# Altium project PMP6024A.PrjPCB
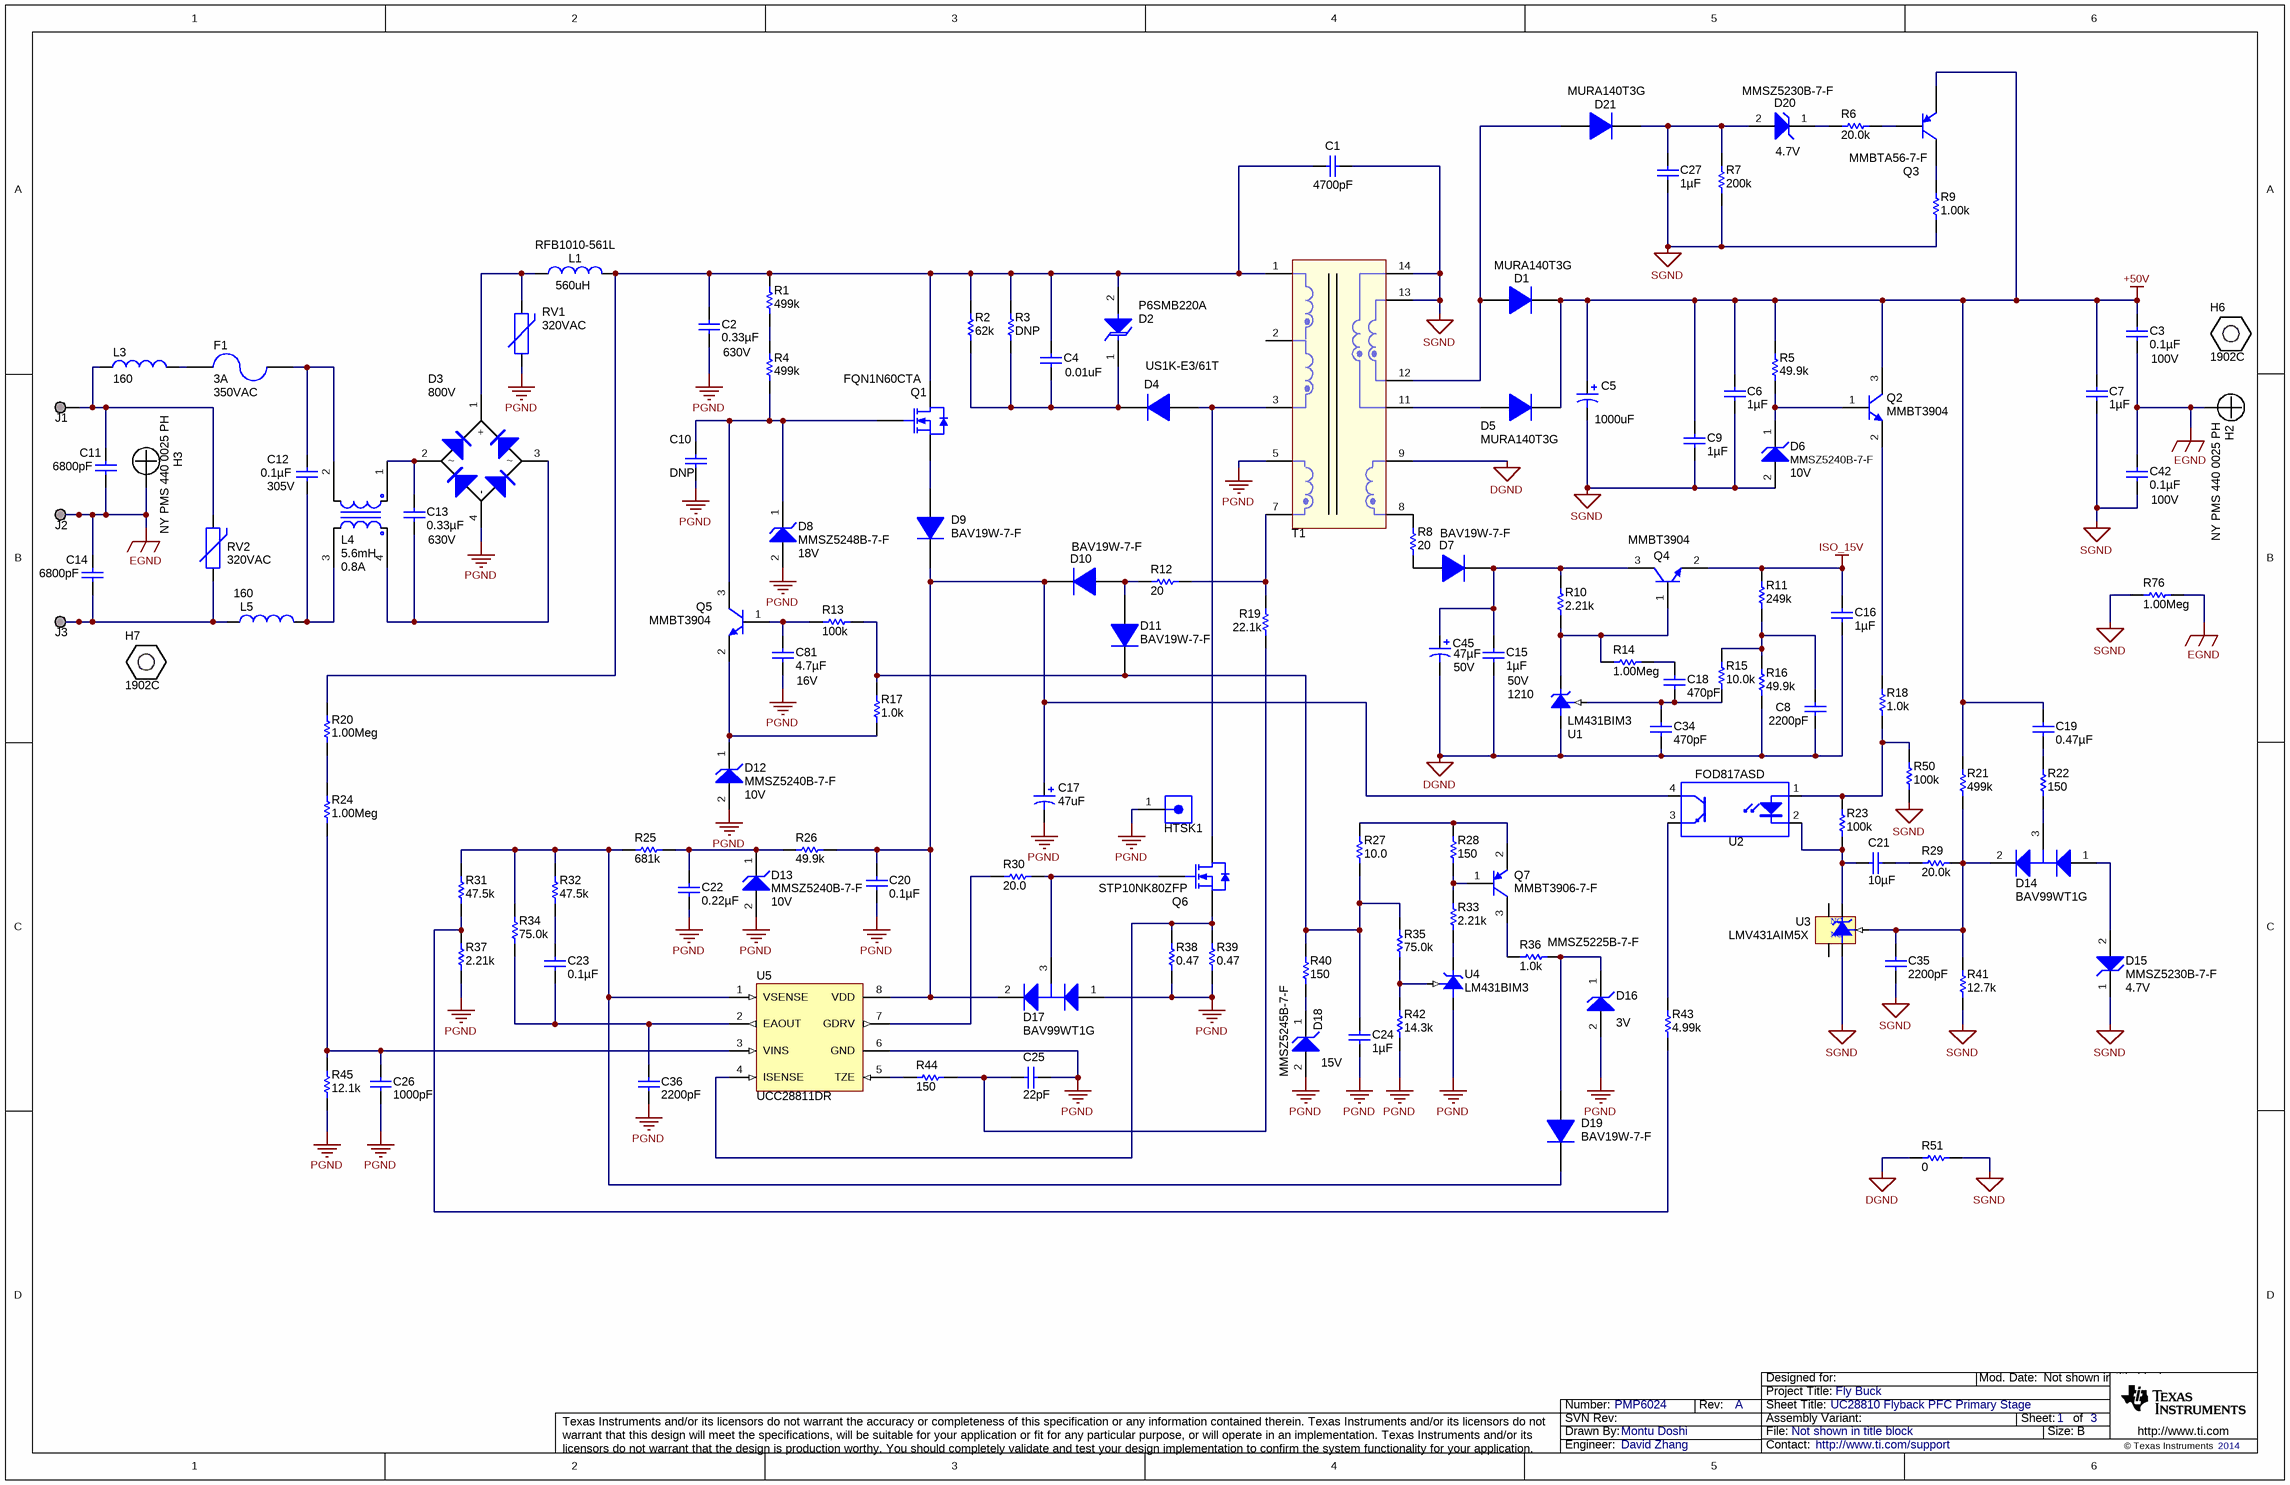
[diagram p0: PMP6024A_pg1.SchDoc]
TechSupport: http://www.ti.com/support; SCH_Rev: A; PRJ_Title: Fly Buck; PRJ_Number: PMP6024; PRJ_Engineer: David Zhang; PCB_Rev: A; PCB_Layout: Kerry Murphy; CopyrightYear: 2014
3 sheets, 186 parts. Net scope: global (net labels, ports and power ports of the same name join across sheets).
Board file: PMP6024A.PcbDoc
Sheets:
  PMP6024A_pg1.SchDoc
  PMP6024A_pg2.SchDoc
  PMP6024A_Hardware.SchDoc

## Sheet PMP6024A_pg1.SchDoc: UC28810 Flyback PFC Primary Stage
size 431 x 279 mm; Date: Not shown in title block; ApprovedBy: Not shown in title block; CheckedBy: Not shown in title block; Author: Not shown in title block; CompanyName: Not shown in title block; DrawnBy: Montu Doshi; Engineer: Not shown in title block; Organization: Not shown in title block; Address1: Not shown in title block; Address2: Not shown in title block; Address3: Not shown in title block; Address4: Not shown in title block; DocumentNumber: 1; Revision: Use project parameter SCH_Rev; SheetNumber: 1; SheetTotal: 3; PageSetup: Record=PageOptions|CenterHorizontal=True|CenterVertical=True|PrintScale=1.00|XCorrection=1.00|YCorrection=1.00|PrintKind=0|BorderSize=5000000|LeftOffset=0|BottomOffset=0|Orientation=2|PaperLength=1000|PaperWidth=1000|Scale=100|PaperSource=15|PrintQuality=600|MediaType=1|DitherType=10|PaperKind=Letter|PrintScaleMode=1

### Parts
C1  value 4700pF  [Cap_NP_16Dx5W-10LS]  (hidden comment: VY1472M63Y5UQ63V0)
C2  ValueDisplayed: 0.33µF  Value2: 630V  [B32922_14.5mm]  (hidden comment: B32922C3334M)
C3  ValueDisplayed: 0.1µF  Value2: 100V  [1206]  (hidden comment: GRM319R72A104KA01D)
C4  value 0.01uF  [1808]  (hidden comment: VJ1808Y103KXGAT)
C5  value 1000uF  [CAP_POL-16.5Dx37.5T-7.5LS_Horz]  (hidden comment: UPW1J102MHD6)
C6  ValueDisplayed: 1µF  [1206]  (hidden comment: GRM31CR72A105KA01L)
C7  ValueDisplayed: 1µF  [1206]  (hidden comment: GRM31CR72A105KA01L)
C8  ValueDisplayed: 2200pF  [0603_HV]  (hidden comment: C0603C222K5RACTU)
C9  ValueDisplayed: 1µF  [1206]  (hidden comment: GRM31CR72A105KA01L)
C10  DNP  [0603_HV]
C11  value 6800pF  [Cap_NP_14.5Lx5W-10LS]  (hidden comment: VY2682M59Y5US63V0)
C12  value 0.1µF  Voltage Rating - AC: 305V  [Cap_NP_13Lx6W-10LS]  (hidden comment: B32921C3104M)
C13  ValueDisplayed: 0.33µF  Value2: 630V  [B32922_14.5mm]  (hidden comment: B32922C3334M)
C14  value 6800pF  [Cap_NP_14.5Lx5W-10LS]  (hidden comment: VY2682M59Y5US63V0)
C15  ValueDisplayed: 1µF  Value2: 50V  [1210]  (hidden comment: GRM32RR71H105KA01L)
C16  ValueDisplayed: 1µF  [1206]  (hidden comment: GRM31CR72A105KA01L)
C17  value 47uF  [Cap_Pol_5Dx11T-2LS]  (hidden comment: EEU-EB1E470S)
C18  ValueDisplayed: 470pF  [0603_HV]  (hidden comment: GRM1885C2A471JA01D)
C19  ValueDisplayed: 0.47µF  [1206]  (hidden comment: GRM31MR72A474KA35L)
C20  ValueDisplayed: 0.1µF  [0603_HV]  (hidden comment: GRM188R71H104KA93D)
C21  ValueDisplayed: 10µF  [1206]  (hidden comment: GRM31CR71A106KA01L)
C22  ValueDisplayed: 0.22µF  [0603_HV]  (hidden comment: GRM188R71E224KA88D)
C23  ValueDisplayed: 0.1µF  [0603_HV]  (hidden comment: GRM188R71H104KA93D)
C24  ValueDisplayed: 1µF  [1206]  (hidden comment: GRM31CR72A105KA01L)
C25  ValueDisplayed: 22pF  [0603_HV]  (hidden comment: GRM1885C2A220JA01D)
C26  ValueDisplayed: 1000pF  [0603_HV]  (hidden comment: GRM188R72A102KA01D)
C27  ValueDisplayed: 1µF  [1206]  (hidden comment: GRM31CR72A105KA01L)
C34  ValueDisplayed: 470pF  [0603_HV]  (hidden comment: GRM1885C2A471JA01D)
C35  ValueDisplayed: 2200pF  [0603_HV]  (hidden comment: C0603C222K5RACTU)
C36  ValueDisplayed: 2200pF  [0603_HV]  (hidden comment: C0603C222K5RACTU)
C42  ValueDisplayed: 0.1µF  Value2: 100V  [1206]  (hidden comment: GRM319R72A104KA01D)
C45  value 47µF  VDC_V: 50V  [Cap_Pol_6.3Dx11T-2.5LS_horz]  (hidden comment: UPW1H470MED)
C81  ValueDisplayed: 4.7µF  VDC_V: 16V  [0805_HV]  (hidden comment: C2012X5R1C475K125AC)
D1  MURA140T3G  [SMA]
D2  P6SMB220A  [SMB]
D3  value 800V  [KBPM]  (hidden comment: 2KBP08M-E4/51)
D4  US1K-E3/61T  [SMA]
D5  MURA140T3G  [SMA]
D6  MMSZ5240B-7-F  value 10V  [SOD-123]
D7  BAV19W-7-F  [SOD-123]
D8  MMSZ5248B-7-F  value 18V  [SOD-123]
D9  BAV19W-7-F  [SOD-123]
D10  BAV19W-7-F  [SOD-123]
D11  BAV19W-7-F  [SOD-123]
D12  MMSZ5240B-7-F  value 10V  [SOD-123]
D13  MMSZ5240B-7-F  value 10V  [SOD-123]
D14  BAV99WT1G  [SOT-323]
D15  MMSZ5230B-7-F  value 4.7V  [SOD-123]
D16  MMSZ5225B-7-F  value 3V  [SOD-123]
D17  BAV99WT1G  [SOT-323]
D18  MMSZ5245B-7-F  value 15V  [SOD-123]
D19  BAV19W-7-F  [SOD-123]
D20  MMSZ5230B-7-F  value 4.7V  [SOD-123]
D21  MURA140T3G  [SMA]
F1  value 3A  Value1: 350VAC  [Fuse_447series]  (hidden comment: 0447003.YXP)
H2  NY PMS 440 0025 PH  [NY PMS 440 0025 PH]
H3  NY PMS 440 0025 PH  [NY PMS 440 0025 PH]
H6  1902C  [Keystone_1902C]
H7  1902C  [Keystone_1902C]
HTSK1  7141DG  [Htsk_7147DG]  (value not drawn)
J1  TESTPOINT  [Hole_R110D70]  (value not drawn)  (no BOM)
J2  TESTPOINT  [Hole_R110D70]  (value not drawn)  (no BOM)
J3  TESTPOINT  [Hole_R110D70]  (value not drawn)  (no BOM)
L1  value 560uH  [Indt_RL5480-4]  (hidden comment: RFB1010-561L)
L3  value 160  [1206]  (hidden comment: HI1206T161R-10)
L4  value 5.6mH  Value1: 0.8A  [Schaffner_EH20-0.8-02-5M6]  (hidden comment: EH20-0.8-02-5M6)
L5  value 160  [1206]  (hidden comment: HI1206T161R-10)
Q1  FQN1N60CTA  [TO92_modified]
Q2  MMBT3904  [MF03A_N]
Q3  MMBTA56-7-F  [MF03A_N]
Q4  MMBT3904  [MF03A_N]
Q5  MMBT3904  [MF03A_N]
Q6  STP10NK80ZFP  [TO-220AB-wide]
Q7  MMBT3906-7-F  [MF03A_N]
R1  value 499k  [1206]  (hidden comment: CRCW1206499KFKEA)
R2  value 62k  [2512]  (hidden comment: CRCW251262K0JNEG)
R3  DNP  [2512]
R4  value 499k  [1206]  (hidden comment: CRCW1206499KFKEA)
R5  value 49.9k  [0603_HV]  (hidden comment: CRCW060349K9FKEA)
R6  value 20.0k  [0603]  (hidden comment: CRCW060320K0FKEA)
R7  value 200k  [1206]  (hidden comment: CRCW1206200KFKEA)
R8  value 20  [1206]  (hidden comment: CRCW120620R0JNEA)
R9  value 1.00k  [0603]  (hidden comment: CRCW06031K00FKEA)
R10  value 2.21k  [0603_HV]  (hidden comment: CRCW06032K21FKEA)
R11  value 249k  [0603_HV]  (hidden comment: CRCW0603249KFKEA)
R12  value 20  [1206]  (hidden comment: CRCW120620R0JNEA)
R13  value 100k  [0603_HV]  (hidden comment: CRCW0603100KFKEA)
R14  value 1.00Meg  [0603_HV]  (hidden comment: CRCW06031M00FKEA)
R15  value 10.0k  [0603_HV]  (hidden comment: CRCW060310K0FKEA)
R16  value 49.9k  [0603_HV]  (hidden comment: CRCW060349K9FKEA)
R17  value 1.0k  [0603_HV]  (hidden comment: CRCW06031K00JNEA)
R18  value 1.0k  [0603_HV]  (hidden comment: CRCW06031K00JNEA)
R19  value 22.1k  [1206]  (hidden comment: CRCW120622K1FKEA)
R20  value 1.00Meg  [1206]  (hidden comment: CRCW12061M00FKEA)
R21  value 499k  [1206]  (hidden comment: CRCW1206499KFKEA)
R22  value 150  [0805_HV]  (hidden comment: CRCW0805150RFKEA)
R23  value 100k  [0603_HV]  (hidden comment: CRCW0603100KFKEA)
R24  value 1.00Meg  [1206]  (hidden comment: CRCW12061M00FKEA)
R25  value 681k  [0603_HV]  (hidden comment: CRCW0603681KFKEA)
R26  value 49.9k  [0603_HV]  (hidden comment: CRCW060349K9FKEA)
R27  value 10.0  [0603_HV]  (hidden comment: CRCW060310R0FKEA)
R28  value 150  [0805_HV]  (hidden comment: CRCW0805150RFKEA)
R29  value 20.0k  [0603_HV]  (hidden comment: CRCW060320K0FKEA)
R30  value 20.0  [0603_HV]  (hidden comment: CRCW060320R0FKEA)
R31  value 47.5k  [0603_HV]  (hidden comment: CRCW060347K5FKEA)
R32  value 47.5k  [0603_HV]  (hidden comment: CRCW060347K5FKEA)
R33  value 2.21k  [0603_HV]  (hidden comment: CRCW06032K21FKEA)
R34  value 75.0k  [0603_HV]  (hidden comment: CRCW060375K0FKEA)
R35  value 75.0k  [0603_HV]  (hidden comment: CRCW060375K0FKEA)
R36  value 1.0k  [0603_HV]  (hidden comment: CRCW06031K00JNEA)
R37  value 2.21k  [0603_HV]  (hidden comment: CRCW06032K21FKEA)
R38  value 0.47  [1210]  (hidden comment: MCR25JZHFLR470)
R39  value 0.47  [1210]  (hidden comment: MCR25JZHFLR470)
R40  value 150  [0805_HV]  (hidden comment: CRCW0805150RFKEA)
R41  value 12.7k  [0603_HV]  (hidden comment: CRCW060312K7FKEA)
R42  ValueDisplayed: 14.3k  [0603_HV]  (hidden comment: CRCW060314K3FKEA)
R43  value 4.99k  [0603_HV]  (hidden comment: CRCW06034K99FKEA)
R44  value 150  [0805_HV]  (hidden comment: CRCW0805150RFKEA)
R45  value 12.1k  [0603_HV]  (hidden comment: CRCW060312K1FKEA)
R50  value 100k  [0603]  (hidden comment: CRCW0603100KFKEA)
R51  value 0  [1206]  (hidden comment: CRCW12060000Z0EA)
R76  value 1.00Meg  [1206]  (hidden comment: CRCW12061M00FKEA)
RV1  value 320VAC  [MOV_S14K320E2K1]  (hidden comment: S14K320E2K1)
RV2  value 320VAC  [MOV_S14K320E2K1]  (hidden comment: S14K320E2K1)
T1  (no value)  [Xfmr_ETD29H_Wurth]
U1  LM431BIM3  [MF03A_N]
U2  FOD817ASD  [FOD81XASD]
U3  LMV431AIM5X  [MF05A_N]
U4  LM431BIM3  [MF03A_N]
U5  UCC28811DR  [D0008A_N]

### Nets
+50V: C3.1 C5.1(+) C6.1 C7.1 C9.1 C19.1 D1.1(K) D5.1(K) Q2.3(C) Q3.2(E) R5.2 R21.1
DGND: C8.2 C15.2 C16.2 C34.2 C45.2(-) R16.1 R51.1 T1.9 U1.3(A)
EGND: C3.2 C11.2 C14.1 C42.1 H2.1(P1) H3.1(P1) J2.1 R76.1
ISO_15V: C16.1 Q4.2(E) R11.2
PGND: C2.2 C10.2 C17.2(-) C20.2 C22.2 C24.2 C25.1 C26.2 C36.2 C81.2 D3.4(-) D8.2(A) D12.2(A) D13.2(A) D16.2(A) D17.1(A) D18.2(A) HTSK1.1 R37.1 R38.1 R39.1 R42.1 R45.1 RV1.1 T1.5 U4.3(A) U5.6(GND)
SGND: C1.1 C5.2(-) C6.2 C7.2 C9.2 C27.2 C35.2 C42.2 D6.2(A) D15.1(K) R7.1 R9.1 R41.1 R50.1 R51.2 R76.2 T1.13 T1.14 U3.5(A)
NetC1_2: C1.2 C2.1 C4.1 D2.2(A) L1.2 Q1.2(D) R1.1 R2.2 R3.2 R20.2 T1.1
NetC4_2: C4.2 D2.1(K) D4.1(K) R2.1 R3.1
NetC8_1: C8.1 R11.1 R15.2 R16.2
NetC10_1: C10.1 D8.1(K) Q1.1(G) Q5.3(C) R4.2
NetC11_1: C11.1 J1.1 L3.1 RV2.2
NetC12_1: C12.1 F1.1 L4.2
NetC12_2: C12.2 L4.3 L5.2
NetC13_1: C13.1 D3.2 L4.1
NetC13_2: C13.2 D3.3 L4.4
NetC14_2: C14.2 J3.1 L5.1 RV2.1
NetC15_1: C15.1 C45.1(+) D7.1(K) Q4.3(C) R10.2
NetC17_1: C17.1(+) C20.1 D9.1(K) D10.1(K) D17.2(K) R26.2 U2.4(C) U5.8(VDD)
NetC18_1: C18.1 R14.1
NetC18_2: C18.2 C34.1 R15.1 U1.2(REF)
NetC19_2: C19.2 R22.2
NetC21_1: C21.1 R23.1 U2.2(K) U3.3(K)
NetC21_2: C21.2 R29.2
NetC22_1: C22.1 D13.1(K) R25.1 R26.1
NetC23_1: C23.1 R32.1
NetC23_2: C23.2 C36.1 R34.1 U5.2(EAOUT)
NetC24_1: C24.1 D11.1(K) R13.2 R17.2 R27.1 R35.2 R40.2
NetC25_2: C25.2 R19.1 R44.1
NetC26_1: C26.1 R24.1 R45.2 U5.3(VINS)
NetC27_1: C27.1 D20.2(A) D21.1(K) R7.2
NetC35_1: C35.1 D14.2(K) R21.2 R29.1 R41.2 U3.4(REF)
NetC81_1: C81.1 Q5.1(B) R13.1
NetD1_2: D1.2(A) D21.2(A) T1.12
NetD3_1: D3.1(+) L1.1 RV1.2
NetD4_2: D4.2(A) Q6.2(D) T1.3
NetD5_2: D5.2(A) T1.11
NetD6_1: D6.1(K) Q2.1(B) R5.1
NetD7_2: D7.2(A) R8.2
NetD9_2: D9.2(A) Q1.3(S)
NetD10_2: D10.2(A) D11.2(A) R12.2
NetD12_1: D12.1(K) Q5.2(E) R17.1
NetD14_1: D14.1(A) D15.2(A)
NetD14_3: D14.3(C) R22.1
NetD16_1: D16.1(K) D19.2(A) R36.2
NetD17_3: D17.3(C) Q6.1(G) R30.2
NetD18_1: D18.1(K) R40.1
NetD19_1: D19.1(K) R25.2 R31.2 R32.2 R34.2 U5.1(VSENSE)
NetD20_1: D20.1(K) R6.1
NetF1_2: F1.2 L3.2
NetQ2_2: Q2.2(E) R18.2
NetQ3_1: Q3.1(B) R6.2
NetQ3_3: Q3.3(C) R9.2
NetQ4_1: Q4.1(B) R10.1 R14.2 U1.1(K)
NetQ6_3: Q6.3(S) R38.2 R39.2 U5.4(ISENSE)
NetQ7_1: Q7.1(B) R28.1 R33.2
NetQ7_2: Q7.2(E) R27.2 R28.2
NetQ7_3: Q7.3(C) R36.1
NetR1_2: R1.2 R4.1
NetR8_1: R8.1 T1.8
NetR12_1: R12.1 R19.2 T1.7
NetR18_1: R18.1 R23.2 R50.2 U2.1(A)
NetR20_1: R20.1 R24.2
NetR30_1: R30.1 U5.7(GDRV)
NetR31_1: R31.1 R37.2 R43.1
NetR33_1: R33.1 U4.1(K)
NetR35_1: R35.1 R42.2 U4.2(REF)
NetR43_2: R43.2 U2.3(E)
NetR44_2: R44.2 U5.5(TZE)

Not connected (* = marked no-connect by the designer): T1 2 4 6 10; U3 1(NC) 2(NC)

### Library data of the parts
C1 = Capacitor: CAP, CERM, 4700pF, 500VAC, Y5U, 20%, Radial 10mm; Manufacturer: Vishay BC Components; Polarized: N; U/M: EA
C2 C13 = B32922C3334M: CAP, Film, 0.33uF, 630V, +/-20%, TH; Manufacturer: EPCOS Inc; Polarized: N; CompType: Capacitor; U/M: EA; Cap_F: 0.00000033; Tolerance_%: 20; Value1: Unknown; VDC_V: 630; TaMax_C: 110
C3 C42 = GRM319R72A104KA01D: CAP, CERM, 0.1uF, 100V, +/-10%, X7R, 1206; Manufacturer: MuRata; Polarized: N; CompType: Capacitor; U/M: EA; Cap_F: 0.0000001; Tolerance_%: 10; VDC_V: 100; TaMin_C: -55; TaMax_C: 125
C4 = Capacitor: CAP, CERM, 0.01uF, 1000V, X7R, 10%, 1808; Manufacturer: Vishay Vitramon; Alternate Manufacturer: Kemet; Alternate PartNumber: C1808C103KDRACTU; Polarized: N; U/M: EA
C5 = Capacitor_Polarized: CAP, Aluminum, 1000uF, 63V, +/-20%, Radial; Manufacturer: Panasonic Electronic Components; Polarized: Y; U/M: EA
C6 C7 C9 C16 C24 C27 = GRM31CR72A105KA01L: CAP, CERM, 1uF, 100V, +/-10%, X7R, 1206; Manufacturer: MuRata; Polarized: N; CompType: Capacitor; U/M: EA; Cap_F: 0.000001; Tolerance_%: 10; VDC_V: 100; TaMin_C: -55; TaMax_C: 125; Cap_Case: 2220
C8 C35 C36 = C0603C222K5RACTU: CAP, CERM, 2200pF, 50V, +/-10%, X7R, 0603; Manufacturer: Kemet; Polarized: N; CompType: Capacitor; U/M: EA; Cap_F: 0.0000000022; Tolerance_%: 10; Value1: Unknown; VDC_V: 50; TaMin_C: -55; TaMax_C: 125; Cap_Case: 0603
C10 = GRM188R71E473KA01D: Manufacturer: MuRata; Polarized: N; CompType: Capacitor; U/M: EA; Tolerance_%: 10; VDC_V: 25; Value2: 25V; TempCo: X7R; TaMin_C: -55; TaMax_C: 125; Cap_Case: 0603
C11 C14 = Capacitor: CAP, Safety, 6800pF, 300VAC, Y5U, 20%, Radial, Disc; Manufacturer: Vishay BC Components; Polarized: N; U/M: EA; Description: CAP CER 6800PF 300V 20% RADIAL; TempCo: Y5U (E); Ratings: X1Y2
C12 = Capacitor: CAP, FILM, 0.1uF, 305VAC, Radial; Manufacturer: EPCOS Inc; Polarized: N; U/M: EA; Voltage Rating - DC: 630V; Description: CAP FILM 0.1UF 305VAC RADIAL; Tolerance_%: ±20%; Dielectric Material: Polypropylene
C15 = GRM32RR71H105KA01L: CAP, CERM, 1uF, 50V, +/-10%, X7R, 1210; Manufacturer: MuRata; Polarized: N; CompType: Capacitor; U/M: EA; Cap_F: 0.000001; Tolerance_%: 10; ESR_Ohm: 0.003; Value1: 0.003 ohm; VDC_V: 50; TaMin_C: -30; TaMax_C: 85
C17 = Capacitor_Polarized: CAP, Aluminum, 47uF, 25V, +/-20%, Radial; Manufacturer: Panasonic Electronic Components; Polarized: Y; U/M: EA
C18 C34 = GRM1885C2A471JA01D: CAP, CERM, 470pF, 100V, +/-5%, C0G/NP0, 0603; Manufacturer: MuRata; Polarized: N; CompType: Capacitor; U/M: EA; Cap_F: 0.00000000047; Tolerance_%: 5; Value1: Unknown; VDC_V: 100; TaMin_C: -55; TaMax_C: 125; Cap_Case: 0603
C19 = GRM31MR72A474KA35L: CAP, CERM, 0.47uF, 100V, +/-10%, X7R, 1206; Manufacturer: MuRata; Polarized: N; CompType: Capacitor; U/M: EA; Cap_F: 0.00000047; Tolerance_%: 10; VDC_V: 100; TaMin_C: -55; TaMax_C: 125
C20 C23 = GRM188R71H104KA93D: CAP, CERM, 0.1uF, 50V, +/-10%, X7R, 0603; Manufacturer: MuRata; Polarized: N; CompType: Capacitor; U/M: EA; Cap_F: 0.0000001; Tolerance_%: 10; VDC_V: 50; TaMin_C: -55; TaMax_C: 125; Cap_Case: 0603
C21 = GRM31CR71A106KA01L: CAP, CERM, 10uF, 10V, +/-10%, X5R, 1206; Manufacturer: MuRata; Polarized: N; CompType: Capacitor; U/M: EA; Cap_F: 0.00001; Tolerance_%: 10; TaMin_C: -55; TaMax_C: 85
C22 = GRM188R71E224KA88D: CAP, CERM, 0.22uF, 25V, +/-10%, X7R, 0603; Manufacturer: MuRata; Polarized: N; CompType: Capacitor; U/M: EA; Cap_F: 0.00000022; Tolerance_%: 10; VDC_V: 25; TaMin_C: -55; TaMax_C: 125; Cap_Case: 0603
C25 = GRM1885C2A220JA01D: CAP, CERM, 22pF, 100V, +/-5%, C0G/NP0, 0603; Manufacturer: MuRata; Polarized: N; CompType: Capacitor; U/M: EA; Cap_F: 0.000000000022; Tolerance_%: 5; VDC_V: 100; TaMin_C: -55; TaMax_C: 125; Cap_Case: 0603
C26 = GRM188R72A102KA01D: CAP, CERM, 1000pF, 100V, +/-10%, X7R, 0603; Manufacturer: MuRata; Polarized: N; CompType: Capacitor; U/M: EA; Cap_F: 0.000000001; Tolerance_%: 10; VDC_V: 100; TaMin_C: -55; TaMax_C: 125; Cap_Case: 0603
C45 = Capacitor_Polarized: CAP, Alum, 47uF, 50V, +/-20%, Radial; Manufacturer: Nichicon; Polarized: Y; U/M: EA; Description: CAP ALUM 47UF 50V 20% RADIAL; Ripple Current: 300mA; Tolerance_%: ±20%; Impedance: 430 mOhm; Lifetime @ Temp.: 2000 Hrs @ 105°C
C81 = EMK212BJ475KG-T: CAP, CERM, 4.7uF, 16V, +/-10%, X5R, 0805; Manufacturer: TDK Corporation; Polarized: N; CompType: Capacitor; Value: 4.7µF; U/M: EA; Cap_F: 0.0000047; Tolerance_%: ±10%; Value1: Unknown; TaMin_C: -55; TaMax_C: 85; Cap_Case: 0805; Description: CAP CER 4.7UF 16V 10% X5R 0805
D1 D5 D21 = Diode: Diode, Ultrafas, 400V, 2A, SMA; Manufacturer: ON Semiconductor; U/M: EA
D2 = TVS_Diode_Uni: Diode, TVS, Uni, 600W, 220V, Unidirection, 5%, SMB; Manufacturer: Littelfuse Inc; Alternate PartNumber: SMBJ220A; U/M: EA
D3 = Diode_Bridge_Pos1_Neg4_AC23: Diode, Switching-Bridge, 800V, 2A, SIP; Manufacturer: Vishay Semiconductor Diodes Division; CompType: Diode Bridge; U/M: EA
D4 = Diode: Diode, Ultrafast, 800V, 1A, SMA; Manufacturer: Vishay Semiconductor Diodes Division; Alternate Manufacturer: Diodes Inc; Alternate PartNumber: US1K-13-F; U/M: EA
D6 D12 D13 = MMSZ5240B-7-F: Diode, Zener, 10V, 500mW, SOD-123; Manufacturer: Diodes Inc.; U/M: EA; Power_W: 0.5; Vz_V: 10; Value1: 0.5W; RJA_CperW: 350
D7 D9-D11 D19 = Diode: Diode, Fast, 100V, 200mA, SOD-123; Manufacturer: Diodes Inc; Alternate Manufacturer: ON Semiconductor; Alternate PartNumber: MMSD4148T3G; U/M: EA
D8 = MMSZ5248B-7-F: Diode, Zener, 18V, 500mW, SOD-123; Manufacturer: Diodes Inc.; U/M: EA; Power_W: 0.5; Vz_V: 18; Value1: 0.5W; RJA_CperW: 350
D14 D17 = BAV99WT1G: Diode, P-N, 70V, 0.2A, SOT-323; Manufacturer: Fairchild Semiconductor; Value: 0.63V; U/M: EA; Vf_V: 0.63; Io_A: 0.2; Vr_V: 70; TJmax_C: 150
D15 D20 = MMSZ5230B-7-F: Diode, Zener, 4.7V, 500mW, SOD-123; Manufacturer: Diodes Inc.; U/M: EA; Power_W: 0.5; Vz_V: 4.7; Value1: 0.5W; RJA_CperW: 350
D16 = MMSZ5225B-7-F: Diode, Zener, 3V, 500mW, SOD-123; Manufacturer: Diodes Inc.; U/M: EA; Power_W: 0.5; Vz_V: 3; Value1: 0.5W; RJA_CperW: 350
D18 = MMSZ5245B-7-F: Diode, Zener, 15V, 500mW, SOD-123; Manufacturer: Diodes Inc.; U/M: EA; Power_W: 0.5; Vz_V: 15; Value1: 0.5W; RJA_CperW: 350
F1 = Fuse: Fuse, 3A, 350VAC, Board Mount; Manufacturer: Littelfuse Inc; U/M: EA
H2 H3 = Chassis Screw: Machine Screw, Round, #4-40 x 1/4, Nylon, Philips panhead; Manufacturer: B&F Fastener Supply; CompType: Hardware; SymbolCreator: codlsc; U/M: EA
H6 H7 = 1902C: Standoff, Hex, 0.5"L #4-40 Nylon; Manufacturer: Keystone; CompType: Hardware
HTSK1 = Htsk_7141DG: HTSK, Aavid P/N 7141DG, TO-220 Vert, PCB mount; Manufacturer: Aavid Thermalloy; CompType: Heatsink; U/M: EA; Shape: Rectangular; Thermal Resistance @ Forced Air Flow: 10.0°C/W @ 200 LFM; Material Finish: Tin; Thermal Resistance @ Natural: 20.3°C/W; Power Dissipation @ Temperature Rise: 1W @ 30°C; Attachment Method: Clip and PC Pin
J1-J3 = TESTPOINT: TEST POINT.  No entry in BOM.
L1 = Inductor: Inductor, 560uH, 1.05A, Radial; Manufacturer: Coilcraft; U/M: EA
L3 L5 = Inductor: Inductor, Ferrite EMI Chip, 160 Ohm @ 100KHz, 6A, 18m ohm, SMT; Manufacturer: Laird-Signal Integrity Products; U/M: EA
L4 = INDUCTOR_COUPLED: Coupled Inductor, 5.6mH, 0.8A, 245m ohm, +/-15%, Through Hole; Manufacturer: Schaffner EMC Inc; U/M: EA
Q1 = MOSFET_N: MOSFET, N-CH, 600V, 300mA, TO-92; Manufacturer: Fairchild Semiconductor; U/M: EA
Q2 Q4 Q5 = MMBT3904, Fairchild Semiconductor: Transistor, NPN, 40V, 0.2A, SOT-23; Alternate Manufacturer: None; CompType: BJT; U/M: EA; PNP: 0; NPN: 1; Vceo_V: 40; Vcesat1_V: 0.2; Value: 0.2V; HfeMax: 300
Q3 = PNP: Transistor, PNP, 80V, SOT23; Manufacturer: Diodes Inc; CompType: Bipolar Transistor; U/M: EA; Vce Saturation (Max) @ Ib, Ic: 250mV @ 10mA, 100mA; Power - Max: 300mW; Current - Collector (Ic) (Max): 500mA; DC Current Gain (hFE) (Min) @ Ic, Vce: 100 @ 100mA, 1V; Frequency - Transition: 50MHz; Description: TRANSISTOR PNP 80V SOT23-3
Q6 = MOSFET_N: MOSFET, N-CH, 800V, 9A, TO-220FP; Manufacturer: STMicroelectronics; U/M: EA
Q7 = MMBT3906-7-F, Diodes Inc.: Transistor, PNP, 40V, 0.2A, SOT-23; Alternate Manufacturer: None; CompType: BJT; U/M: EA; PNP: 1; NPN: 0; Vceo_V: 40; Vcesat1_V: 0.25; Value: 0.25V; IcRated_A: 0.2; HfeMax: 400
R1 R4 R21 = CRCW1206499KFKEA: RES, 499k ohm, 1%, 0.25W, 1206; Manufacturer: Vishay-Dale; Alternate Manufacturer: Any; Alternate PartNumber: Equivalent; CompType: Resistor; Res_ohm: 499000; Tolerance_%: 1; Power_W: 0.25; VDC_V: 200; TempCo: 100 ppm/C; EIA_Code: E96; U/M: EA
R2 = Resistor: RES, 62k ohm, 5%, 1W, 2512; Manufacturer: Vishay Dale; U/M: EA
R3 = Resistor: Manufacturer: Vishay Dale; U/M: EA
R5 R16 R26 = CRCW060349K9FKEA: RES, 49.9k ohm, 1%, 0.1W, 0603; Manufacturer: Vishay-Dale; Alternate Manufacturer: Any; Alternate PartNumber: Equivalent; CompType: Resistor; Res_ohm: 49900; Value_Code: 49k9; Tolerance_%: 1; Power_W: 0.1; VDC_V: 75; TempCo: 100 ppm/C; EIA_Code: E96; U/M: EA
R6 = CRCW060320K0FKEA: RES, 20.0k ohm, 1%, 0.1W, 0603; Manufacturer: Vishay-Dale; CompType: Resistor; Res_ohm: 20000; Value_Code: 20k0; Tolerance_%: 1; Power_W: 0.1; VDC_V: 75; TempCo: 100 ppm/C; EIA_Code: E96; U/M: EA
R7 = CRCW1206200KFKEA: RES, 200k ohm, 1%, 0.25W, 1206; Manufacturer: Vishay-Dale; CompType: Resistor; Res_ohm: 200000; Tolerance_%: 1; Power_W: 0.25; VDC_V: 200; TempCo: 100 ppm/C; EIA_Code: E96; U/M: EA
R8 R12 = CRCW120620R0JNEA: RES, 20 ohm, 5%, 0.25W, 1206; Manufacturer: Vishay-Dale; Alternate Manufacturer: Any; Alternate PartNumber: Equivalent; CompType: Resistor; Value_Code: 20R0; Tolerance_%: 5; Power_W: 0.25; VDC_V: 200; TempCo: 200 ppm/C; EIA_Code: E24; U/M: EA
R9 = CRCW06031K00FKEA: RES, 1.00k ohm, 1%, 0.1W, 0603; Manufacturer: Vishay-Dale; CompType: Resistor; Res_ohm: 1000; Value_Code: 1k00; Tolerance_%: 1; Power_W: 0.1; VDC_V: 75; TempCo: 100 ppm/C; EIA_Code: E96; U/M: EA
R10 R33 R37 = CRCW06032K21FKEA: RES, 2.21k ohm, 1%, 0.1W, 0603; Manufacturer: Vishay-Dale; Alternate Manufacturer: Any; Alternate PartNumber: Equivalent; CompType: Resistor; Res_ohm: 2210; Value_Code: 2k21; Tolerance_%: 1; Power_W: 0.1; VDC_V: 75; TempCo: 100 ppm/C; EIA_Code: E96; U/M: EA
R11 = CRCW0603249KFKEA: RES, 249k ohm, 1%, 0.1W, 0603; Manufacturer: Vishay-Dale; Alternate Manufacturer: Any; Alternate PartNumber: Equivalent; CompType: Resistor; Res_ohm: 249000; Tolerance_%: 1; Power_W: 0.1; VDC_V: 75; TempCo: 100 ppm/C; EIA_Code: E96; U/M: EA
R13 R50 = CRCW0603100KFKEA: RES, 100k ohm, 1%, 0.1W, 0603; Manufacturer: Vishay-Dale; CompType: Resistor; Res_ohm: 100000; Tolerance_%: 1; Power_W: 0.1; VDC_V: 75; TempCo: 100 ppm/C; EIA_Code: E96; U/M: EA
R14 = CRCW06031M00FKEA: RES, 1.00Meg ohm, 1%, 0.1W, 0603; Manufacturer: Vishay-Dale; Alternate Manufacturer: Any; Alternate PartNumber: Equivalent; CompType: Resistor; Res_ohm: 1000000; Value_Code: 1M00; Tolerance_%: 1; Power_W: 0.1; VDC_V: 75; TempCo: 100 ppm/C; EIA_Code: E96; U/M: EA
R15 = CRCW060310K0FKEA: RES, 10.0k ohm, 1%, 0.1W, 0603; Manufacturer: Vishay-Dale; Alternate Manufacturer: Any; Alternate PartNumber: Equivalent; CompType: Resistor; Res_ohm: 10000; Value_Code: 10k0; Tolerance_%: 1; Power_W: 0.1; VDC_V: 75; TempCo: 100 ppm/C; EIA_Code: E96; U/M: EA
R17 R18 R36 = CRCW06031K00JNEA: RES, 1.0k ohm, 5%, 0.1W, 0603; Manufacturer: Vishay-Dale; Alternate Manufacturer: Any; Alternate PartNumber: Equivalent; CompType: Resistor; Res_ohm: 1000; Value_Code: 1k00; Tolerance_%: 5; Power_W: 0.1; VDC_V: 75; TempCo: 200 ppm/C; EIA_Code: E24; U/M: EA
R19 = CRCW120622K1FKEA: RES, 22.1k ohm, 1%, 0.25W, 1206; Manufacturer: Vishay-Dale; Alternate Manufacturer: Any; Alternate PartNumber: Equivalent; CompType: Resistor; Res_ohm: 22100; Value_Code: 22k1; Tolerance_%: 1; Power_W: 0.25; VDC_V: 200; TempCo: 100 ppm/C; EIA_Code: E96; U/M: EA
R20 R24 R76 = CRCW12061M00FKEA: RES, 1.00Meg ohm, 1%, 0.25W, 1206; Manufacturer: Vishay-Dale; Alternate Manufacturer: Any; Alternate PartNumber: Equivalent; CompType: Resistor; Res_ohm: 1000000; Value_Code: 1M00; Tolerance_%: 1; Power_W: 0.25; VDC_V: 200; TempCo: 100 ppm/C; EIA_Code: E96; U/M: EA
R22 R28 R40 R44 = CRCW0805150RFKEA: RES, 150 ohm, 1%, 0.125W, 0805; Manufacturer: Vishay-Dale; Alternate Manufacturer: Any; Alternate PartNumber: Equivalent; CompType: Resistor; Value_Code: 150R; Tolerance_%: 1; Power_W: 0.125; TempCo: 100 ppm/C; EIA_Code: E96; U/M: EA
R23 = CRCW0603100KFKEA: RES, 100k ohm, 1%, 0.1W, 0603; Manufacturer: Vishay-Dale; Alternate Manufacturer: Any; Alternate PartNumber: Equivalent; CompType: Resistor; Res_ohm: 100000; Tolerance_%: 1; Power_W: 0.1; VDC_V: 75; TempCo: 100 ppm/C; EIA_Code: E96; U/M: EA
R25 = CRCW0603681KFKEA: RES, 681k ohm, 1%, 0.1W, 0603; Manufacturer: Vishay-Dale; Alternate Manufacturer: Any; Alternate PartNumber: Equivalent; CompType: Resistor; Res_ohm: 681000; Tolerance_%: 1; Power_W: 0.1; VDC_V: 75; TempCo: 100 ppm/C; EIA_Code: E96; U/M: EA
R27 = CRCW060310R0FKEA: RES, 10.0 ohm, 1%, 0.1W, 0603; Manufacturer: Vishay-Dale; Alternate Manufacturer: Any; Alternate PartNumber: Equivalent; CompType: Resistor; Res_ohm: 10; Value_Code: 10R0; Tolerance_%: 1; Power_W: 0.1; VDC_V: 75; TempCo: 100 ppm/C; EIA_Code: E96; U/M: EA
R29 = CRCW060320K0FKEA: RES, 20.0k ohm, 1%, 0.1W, 0603; Manufacturer: Vishay-Dale; Alternate Manufacturer: Any; Alternate PartNumber: Equivalent; CompType: Resistor; Res_ohm: 20000; Value_Code: 20k0; Tolerance_%: 1; Power_W: 0.1; VDC_V: 75; TempCo: 100 ppm/C; EIA_Code: E96; U/M: EA
R30 = CRCW060320R0FKEA: RES, 20.0 ohm, 1%, 0.1W, 0603; Manufacturer: Vishay-Dale; CompType: Resistor; Res_ohm: 20; Value_Code: 20R0; Tolerance_%: 1; Power_W: 0.1; VDC_V: 75; TempCo: 100 ppm/C; EIA_Code: E96; U/M: EA
R31 R32 = CRCW060347K5FKEA: RES, 47.5k ohm, 1%, 0.1W, 0603; Manufacturer: Vishay-Dale; Alternate Manufacturer: Any; Alternate PartNumber: Equivalent; CompType: Resistor; Res_ohm: 47500; Value_Code: 47k5; Tolerance_%: 1; Power_W: 0.1; VDC_V: 75; TempCo: 100 ppm/C; EIA_Code: E96; U/M: EA
R34 R35 = CRCW060375K0FKEA: RES, 75.0k ohm, 1%, 0.1W, 0603; Manufacturer: Vishay-Dale; Alternate Manufacturer: Any; Alternate PartNumber: Equivalent; CompType: Resistor; Res_ohm: 75000; Value_Code: 75k0; Tolerance_%: 1; Power_W: 0.1; VDC_V: 75; TempCo: 100 ppm/C; EIA_Code: E96; U/M: EA
R38 R39 = MCR25JZHFLR470: RES, 0.47 ohm, 1%, 0.5W, 1210; Manufacturer: Rohm; Alternate Manufacturer: Any; Alternate PartNumber: Equivalent; CompType: Resistor; Value_Code: R470; Tolerance_%: 1; Power_W: 0.5; VDC_V: 0; TempCo: 200 ppm/C; EIA_Code: E96; U/M: EA
R41 = CRCW060312K7FKEA: RES, 12.7k ohm, 1%, 0.1W, 0603; Manufacturer: Vishay-Dale; Alternate Manufacturer: Any; Alternate PartNumber: Equivalent; CompType: Resistor; Res_ohm: 12700; Value_Code: 12k7; Tolerance_%: 1; Power_W: 0.1; VDC_V: 75; TempCo: 100 ppm/C; EIA_Code: E96; U/M: EA
R42 = CRCW060314K3FKEA: RES, 14.3 k, 1%, 0.1 W, 0603; Manufacturer: Vishay-Dale; CompType: Resistor; Res_ohm: 14300; Value: 14.3k; Value_Code: 14k3; Tolerance_%: 1; Power_W: 0.1; Value2: 0.1W; VDC_V: 75; TempCo: 100 ppm/C; EIA_Code: E96; U/M: EA
R43 = CRCW06034K99FKEA: RES, 4.99k ohm, 1%, 0.1W, 0603; Manufacturer: Vishay-Dale; Alternate Manufacturer: Any; Alternate PartNumber: Equivalent; CompType: Resistor; Res_ohm: 4990; Value_Code: 4k99; Tolerance_%: 1; Power_W: 0.1; VDC_V: 75; TempCo: 100 ppm/C; EIA_Code: E96; U/M: EA
R45 = CRCW060312K1FKEA: RES, 12.1k ohm, 1%, 0.1W, 0603; Manufacturer: Vishay-Dale; Alternate Manufacturer: Any; Alternate PartNumber: Equivalent; CompType: Resistor; Res_ohm: 12100; Value_Code: 12k1; Tolerance_%: 1; Power_W: 0.1; VDC_V: 75; TempCo: 100 ppm/C; EIA_Code: E96; U/M: EA
R51 = CRCW12060000Z0EA: RES, 0 ohm, 5%, 0.25W, 1206; Manufacturer: Vishay-Dale; CompType: Resistor; Value_Code: 0000; Tolerance_%: 5; Power_W: 0.25; VDC_V: 200; TempCo: 200 ppm/C; EIA_Code: E24; U/M: EA
RV1 = Varistor_MetalOxide: Varistor, 320VAC, 420VDC, 84J, 14mm, Disc; Manufacturer: EPCOS Inc; SymbolCreator: a0412235; CompType: MOV; U/M: EA; Description: VARISTOR 320V RMS 14MM RADIAL; Varistor Voltage: 510V; Energy: 150J; Current-Surge: 6kA
RV2 = Varistor_MetalOxide: Varistor, 320VAC, 420VDC, 150J, 14mm, Disc; Manufacturer: EPCOS Inc; SymbolCreator: a0412235; CompType: MOV; U/M: EA; Description: VARISTOR 320V RMS 14MM RADIAL; Varistor Voltage: 510V; Current-Surge: 6kA
T1 = TFR_ETD29: Xfmr, ETD Core, 450uH, 64 Np, 26 Ns, 8 Na1, 10 Na2, ETD29/16/10; Manufacturer: Wurth/Midcom; SymbolCreator: a0413916; CompType: Transformer
U1 U4 = LM431BIM3: Adjustable Precision Zener Shunt Regulator, 3-pin SOT-23; Manufacturer: National Semiconductor; PackageTopMarking: N1C*XTT; PowerWise: N; CompType: MiscPower
U2 = Opto-Isolator: Optoisolator, Phototrans Out, 4-SMD; Manufacturer: Fairchild Semiconductor; U/M: EA; Number of Channels: 1; Input Type: DC; Output Type: Transistor; Vce Saturation (Max): 200mV; Current Transfer Ratio (Min): 80% @ 5mA; Current Transfer Ratio (Max): 160% @ 5mA; Current - DC Forward (If): 50mA; Voltage - Isolation: 5000Vrms; Voltage - Output: 70V; Description: OPTOCOUPLER PHOTOTRANS OUT 4-SMD
U3 = LMV431AIM5X: Low-Voltage (1.24V) Adjustable Precision Shunt Regulators, 5-pin SOT-23; Manufacturer: National Semiconductor; PackageTopMarking: N08A*XTT; PowerWise: N; CompType: MiscPower
U5 = UCC28811DR: LED Lighting Power Controller, -40 to +105 degC, 8-pin SOIC (D), Green (RoHS & no Sb/Br); Manufacturer: Texas Instruments; Alternate Manufacturer: None; Alternate PartNumber: Equivalent; Frequency(Max)(kHz): 200; Rating: Catalog; SubFamily: PWM Controller

## Sheet PMP6024A_pg2.SchDoc: FlyBack2
size 431 x 279 mm; Date: Not shown in title block; ApprovedBy: Not shown in title block; CheckedBy: Not shown in title block; Author: Not shown in title block; CompanyName: Not shown in title block; DrawnBy: Montu Doshi; Engineer: Not shown in title block; Organization: Not shown in title block; Address1: Not shown in title block; Address2: Not shown in title block; Address3: Not shown in title block; Address4: Not shown in title block; DocumentNumber: 2; Revision: Use project parameter SCH_Rev; SheetNumber: 2; SheetTotal: 3; PageSetup: Record=PageOptions|CenterHorizontal=True|CenterVertical=True|PrintScale=0.62|XCorrection=1.00|YCorrection=1.00|PrintKind=0|BorderSize=5000000|LeftOffset=0|BottomOffset=0|Orientation=2|PaperLength=1000|PaperWidth=1000|Scale=100|PaperSource=15|PrintQuality=600|MediaType=1|DitherType=10|PaperKind=Letter|PrintScaleMode=1
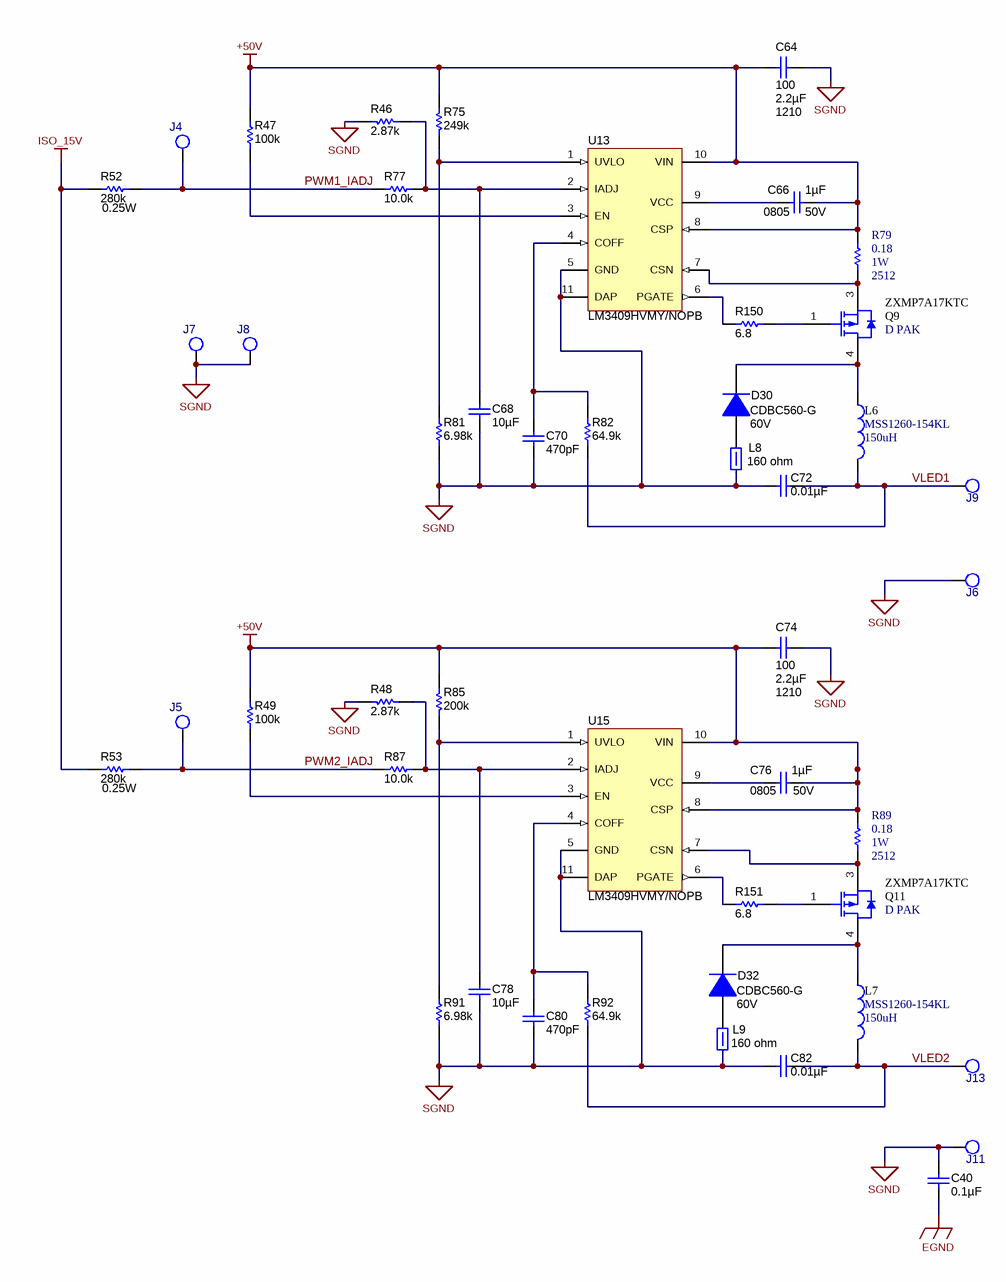
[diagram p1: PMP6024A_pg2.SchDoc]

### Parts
C40  ValueDisplayed: 0.1µF  [0805_HV]  (hidden comment: C0805C104K1RACTU)
C64  VDC_V: 100  ValueDisplayed: 2.2µF  [1210]  (hidden comment: HMK325B7225KN-T)
C66  PackageReference: 0805  Value2: 50V  ValueDisplayed: 1µF  [0805_HV]  (hidden comment: GRM21BR71H105KA12L)
C68  ValueDisplayed: 10µF  [0805_HV]  (hidden comment: GRM21BR61C106KE15L)
C70  ValueDisplayed: 470pF  [0603]  (hidden comment: GRM188R71H471KA01D)
C72  ValueDisplayed: 0.01µF  [0603]  (hidden comment: GRM188R71H103KA01D)
C74  VDC_V: 100  ValueDisplayed: 2.2µF  [1210]  (hidden comment: HMK325B7225KN-T)
C76  PackageReference: 0805  Value2: 50V  ValueDisplayed: 1µF  [0805_HV]  (hidden comment: GRM21BR71H105KA12L)
C78  ValueDisplayed: 10µF  [0805_HV]  (hidden comment: GRM21BR61C106KE15L)
C80  ValueDisplayed: 470pF  [0603]  (hidden comment: GRM188R71H471KA01D)
C82  ValueDisplayed: 0.01µF  [0603]  (hidden comment: GRM188R71H103KA01D)
D30  Vr_V: 60V  [SMC]  (hidden comment: CDBC560-G)
D32  Vr_V: 60V  [SMC]  (hidden comment: CDBC560-G)
J4  NA  [CONN-18GA WIRE]  (value not drawn)
J5  NA  [CONN-18GA WIRE]  (value not drawn)
J6  NA  [CONN-18GA WIRE]  (value not drawn)
J7  NA  [CONN-18GA WIRE]  (value not drawn)
J8  NA  [CONN-18GA WIRE]  (value not drawn)
J9  NA  [CONN-18GA WIRE]  (value not drawn)
J11  NA  [CONN-18GA WIRE]  (value not drawn)
J13  NA  [CONN-18GA WIRE]  (value not drawn)
L6  value 150uH  [MSS1260]  (hidden comment: MSS1260-154KL)
L7  value 150uH  [MSS1260]  (hidden comment: MSS1260-154KL)
L8  value 160 ohm  [1206]  (hidden comment: HI1206T161R-10)
L9  value 160 ohm  [1206]  (hidden comment: HI1206T161R-10)
Q9  ZXMP7A17KTC  PackageReference: D PAK  [DPAK]
Q11  ZXMP7A17KTC  PackageReference: D PAK  [DPAK]
R46  ValueDisplayed: 2.87k  [0603_HV]  (hidden comment: CRCW06032K87FKEA)
R47  value 100k  [0603]  (hidden comment: CRCW0603100KFKEA)
R48  ValueDisplayed: 2.87k  [0603_HV]  (hidden comment: CRCW06032K87FKEA)
R49  value 100k  [0603]  (hidden comment: CRCW0603100KFKEA)
R52  value 280k  Value2: 0.25W  [1206]  (hidden comment: CRCW1206280KFKEA)
R53  value 280k  Value2: 0.25W  [1206]  (hidden comment: CRCW1206280KFKEA)
R75  value 249k  [0603]  (hidden comment: CRCW0603249KFKEA)
R77  value 10.0k  [0603_HV]  (hidden comment: CRCW060310K0FKEA)
R79  value 0.18  Power_W: 1W  [2512]  (hidden comment: ERJ-1TRSJR18U)
R81  value 6.98k  [0603_HV]  (hidden comment: CRCW06036K98FKEA)
R82  value 64.9k  [0603]  (hidden comment: CRCW060364K9FKEA)
R85  value 200k  [0603]  (hidden comment: CRCW0603200KFKEA)
R87  value 10.0k  [0603_HV]  (hidden comment: CRCW060310K0FKEA)
R89  value 0.18  Power_W: 1W  [2512]  (hidden comment: ERJ-1TRSJR18U)
R91  value 6.98k  [0603_HV]  (hidden comment: CRCW06036K98FKEA)
R92  value 64.9k  [0603]  (hidden comment: CRCW060364K9FKEA)
R150  value 6.8  [0603]  (hidden comment: CRCW06036R80JNEA)
R151  value 6.8  [0603]  (hidden comment: CRCW06036R80JNEA)
U13  LM3409HVMY/NOPB  [MUC10A_N]
U15  LM3409HVMY/NOPB  [MUC10A_N]

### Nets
+50V: C64.2 C66.2 C74.2 C76.2 R47.1 R49.1 R75.1 R79.2 R85.1 R89.2 U13.8(CSP) U13.10(VIN) U15.8(CSP) U15.10(VIN)
EGND: C40.2
ISO_15V: R52.1 R53.1
SGND: C40.1 C64.1 C68.2 C70.2 C72.2 C74.1 C78.2 C80.2 C82.2 J6.1 J7.1 J8.1 J11.1 L8.1 L9.1 R46.2 R48.2 R81.1 R91.1 U13.5(GND) U13.11(DAP) U15.5(GND) U15.11(DAP)
PWM1_IADJ: J4.1 R52.2 R77.2
PWM2_IADJ: J5.1 R53.2 R87.2
VLED1: C72.1 J9.1 L6.2 R82.1
VLED2: C82.1 J13.1 L7.2 R92.1
NetC66_1: C66.1 U13.9(VCC)
NetC68_1: C68.1 R46.1 R77.1 U13.2(IADJ)
NetC70_1: C70.1 R82.2 U13.4(COFF)
NetC76_1: C76.1 U15.9(VCC)
NetC78_1: C78.1 R48.1 R87.1 U15.2(IADJ)
NetC80_1: C80.1 R92.2 U15.4(COFF)
NetD30_1: D30.1(K) L6.1 Q9.4(D)
NetD30_2: D30.2(A) L8.2
NetD32_1: D32.1(K) L7.1 Q11.4(D)
NetD32_2: D32.2(A) L9.2
NetQ9_1: Q9.1(G) R150.2
NetQ9_3: Q9.3(S) R79.1 U13.7(CSN)
NetQ11_1: Q11.1(G) R151.2
NetQ11_3: Q11.3(S) R89.1 U15.7(CSN)
NetR47_2: R47.2 U13.3(EN)
NetR49_2: R49.2 U15.3(EN)
NetR75_2: R75.2 R81.2 U13.1(UVLO)
NetR85_2: R85.2 R91.2 U15.1(UVLO)
NetR150_1: R150.1 U13.6(PGATE)
NetR151_1: R151.1 U15.6(PGATE)

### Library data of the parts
C40 = C0805C104K1RACTU: CAP, CERM, 0.1uF, 100V, +/-10%, X7R, 0805; Manufacturer: Kemet; NSC_PartNumber: 151013405-005; Cap_Case: 0805; ESR_Ohm: 0.064; IRMS_A: 1.64; Polarized: N; TaMax_C: 125; TaMin_C: -55; Tolerance_%: 10; VDC_V: 100; Cap_F: 100.0E-9; CompType: Capacitor; Value1: 0.064 ohm
C64 C74 = HMK325B7225KN-T: CAP, CERM, 2.2uF, 100V, +/-10%, X7R, 1210; Manufacturer: Taiyo Yuden; NSC_PartNumber: 151013405-009; Polarized: N; TaMax_C: 125; TaMin_C: -55; Tolerance_%: 10; Cap_F: 2.2E-6; CompType: Capacitor
C66 C76 = GRM21BR71H105KA12L: CAP, CERM, 1uF, 50V, +/-10%, X7R, 0805; Manufacturer: MuRata; NSC_PartNumber: 151008655-105; Polarized: N; TaMax_C: 125; TaMin_C: -55; Tolerance_%: 10; VDC_V: 50; Cap_F: 1.0E-6; CompType: Capacitor
C68 C78 = GRM21BR61C106KE15L: CAP, CERM, 10uF, 16V, +/-10%, X5R, 0805; Manufacturer: MuRata; Polarized: N; CompType: Capacitor; U/M: EA; Cap_F: 0.00001; Tolerance_%: 10; ESR_Ohm: 0.008; Value1: 0.008 ohm; VDC_V: 16; TaMin_C: -55; TaMax_C: 85; Cap_Case: 0805
C70 C80 = GRM188R71H471KA01D: CAP, CERM, 470pF, 50V, +/-10%, X7R, 0603; Manufacturer: MuRata; NSC_PartNumber: 151008797-471; Polarized: N; TaMax_C: 125; TaMin_C: -55; Tolerance_%: 10; VDC_V: 50; Cap_F: 470.0E-12; CompType: Capacitor
C72 C82 = GRM188R71H103KA01D: CAP, CERM, 0.01uF, 50V, +/-10%, X7R, 0603; Manufacturer: MuRata; NSC_PartNumber: 151008797-103; Polarized: N; TaMax_C: 125; TaMin_C: -55; Tolerance_%: 10; VDC_V: 50; Cap_F: 10.0E-9; CompType: Capacitor
D30 D32 = Diode: DIODE SCHOTTKY 60V 5A DO214AB; Manufacturer: Comchip Technology; Value: 750mV @ 5A; U/M: EA; Speed: Fast Recovery =< 500ns, > 200mA (Io); Current - Reverse Leakage @ Vr: 500µA @ 60V
J4-J9 J11 J13 = CONN_18GA HOLE: 18 GA WIRE HOLE; SymbolVersion: use current date i.e. 2008-05-20; SymbolCreator: Use LDAP id
L6 L7 = Inductor: Technology, Imax, DCR; Manufacturer: CoilCraft; NSC_PartNumber: 180008852-154
L8 L9 = HI1206T161R-10: 6A Ferrite Bead, 160 ohm @ 100MHz, SMD; Manufacturer: Steward; Imax_A: 6; DCR_ohm: 0.018; Value1: 0.018 ohm; ZTyp@100MHz_Ohm: 160; Ztyp@1GHz_Ohm: 127; U/M: EA
Q9 Q11 = MOSFET_P: MOSFET P-CH 70V 5.7A D PAK; Manufacturer: Diiodes/Zetex; NSC_PartNumber: 480008978-576
R46 R48 = CRCW06032K87FKEA: RES, 2.87 k, 1%, 0.1 W, 0603; Manufacturer: Vishay-Dale; CompType: Resistor; Res_ohm: 2870; Value: 2.87k; Value_Code: 2k87; Tolerance_%: 1; Power_W: 0.1; Value2: 0.1W; VDC_V: 75; TempCo: 100 ppm/C; EIA_Code: E96; U/M: EA
R47 R49 = CRCW0603100KFKEA: as R23 on sheet PMP6024A_pg1
R52 R53 = CRCW1206280KFKEA: RES, 280k ohm, 1%, 0.25W, 1206; Manufacturer: Vishay-Dale; CompType: Resistor; Res_ohm: 280000; Tolerance_%: 1; Power_W: 0.25; VDC_V: 200; TempCo: 100 ppm/C; EIA_Code: E96; U/M: EA
R75 = CRCW0603249KFKEA: RES, 249k ohm, 1%, 0.1W, 0603; Manufacturer: Vishay-Dale; CompType: Resistor; Res_ohm: 249000; Tolerance_%: 1; Power_W: 0.1; VDC_V: 75; TempCo: 100 ppm/C; EIA_Code: E96; U/M: EA
R77 R87 = CRCW060310K0FKEA: as R15 on sheet PMP6024A_pg1
R79 R89 = Resistor: RES .18 OHM 1W 5% 2512 SMD; Manufacturer: Panasonic -ECG; NSC_PartNumber: 473008540-189; Tolerance_%: 1%
R81 R91 = CRCW06036K98FKEA: RES, 6.98k ohm, 1%, 0.1W, 0603; Manufacturer: Vishay-Dale; NSC_PartNumber: 473008800-482; CompType: Resistor; Tolerance_%: 1; VDC_V: 75; Power_W: 0.1; Res_Ohm: 6980; Value_Code: 6k98; EIA_Code: E96
R82 R92 = CRCW060364K9FKEA: RES, 64.9k ohm, 1%, 0.1W, 0603; Manufacturer: Vishay-Dale; NSC_PartNumber: 473008800-579; CompType: Resistor; Tolerance_%: 1; VDC_V: 75; Power_W: 0.1; Res_Ohm: 64900; Value_Code: 64k9; EIA_Code: E96
R85 = CRCW0603200KFKEA: RES, 200k ohm, 1%, 0.1W, 0603; Manufacturer: Vishay-Dale; CompType: Resistor; Res_ohm: 200000; Tolerance_%: 1; Power_W: 0.1; VDC_V: 75; TempCo: 100 ppm/C; EIA_Code: E96; U/M: EA
R150 R151 = CRCW06036R80JNEA: RES, 6.8 ohm, 5%, 0.1W, 0603; Manufacturer: Vishay-Dale; NSC_PartNumber: 473008776-688; CompType: Resistor; Tolerance_%: 5; VDC_V: 75; Power_W: 0.1; Value_Code: 6R80; EIA_Code: E24; U/M: EA
U13 U15 = LM3409HVMY/NOPB: PFET Buck Controller for High Power LED Drives, 10-pin eMSOP, Pb-Free; Manufacturer: National Semiconductor; PackageTopMarking: ZXTT*SYHB; PowerWise: Y; CompType: MiscPower

## Sheet PMP6024A_Hardware.SchDoc: Hardware
size 431 x 279 mm; Date: Not shown in title block; ApprovedBy: Not shown in title block; CheckedBy: Not shown in title block; Author: Not shown in title block; CompanyName: Not shown in title block; DrawnBy: Montu Doshi; Engineer: Not shown in title block; Organization: Not shown in title block; Address1: Not shown in title block; Address2: Not shown in title block; Address3: Not shown in title block; Address4: Not shown in title block; DocumentNumber: 3; Revision: Use project parameter SCH_Rev; SheetNumber: 3; SheetTotal: 3; PageSetup: Record=PageOptions|CenterHorizontal=True|CenterVertical=True|PrintScale=1.00|XCorrection=1.00|YCorrection=1.00|PrintKind=0|BorderSize=5000000|LeftOffset=0|BottomOffset=0|Orientation=2|PaperLength=1000|PaperWidth=1000|Scale=100|PaperSource=15|PrintQuality=600|MediaType=1|DitherType=10|PaperKind=Letter|PrintScaleMode=1
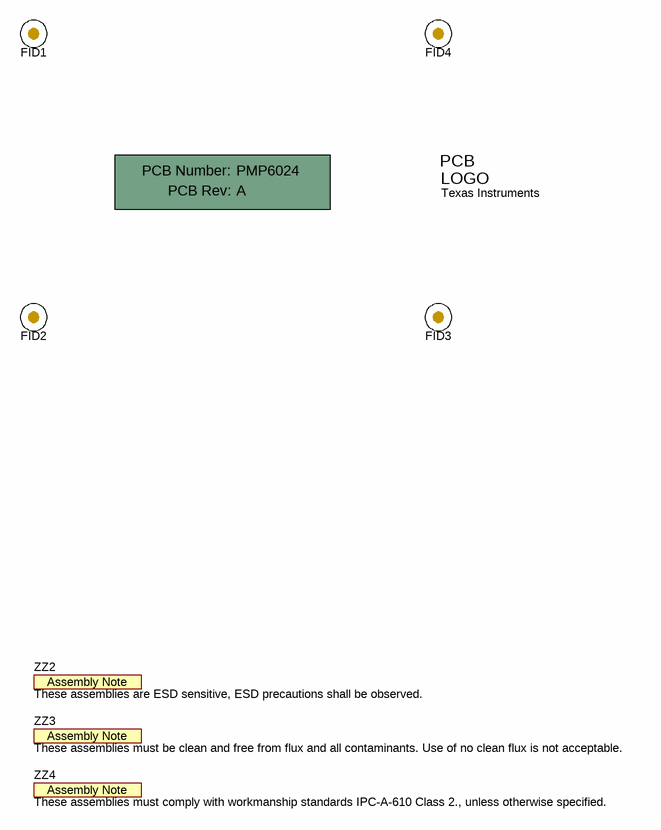
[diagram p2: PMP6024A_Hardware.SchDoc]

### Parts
!PCB  Printed Circuit Board  (value not drawn)  (mechanical)
FID1  Fiducial  [Fiducial10-20]  (value not drawn)
FID2  Fiducial  [Fiducial10-20]  (value not drawn)
FID3  Fiducial  [Fiducial10-20]  (value not drawn)
FID4  Fiducial  [Fiducial10-20]  (value not drawn)
Logo1  Texas Instruments  [TI_Symbol_Overlay_Small]  (no BOM)
ZZ2  These assemblies are ESD sensitive, ESD precautions shall be observed.  [AssemblyNote]  (no BOM)
ZZ3  These assemblies must be clean and free from flux and all contaminants. Use of no clean flux is not acceptable.  [AssemblyNote]  (no BOM)
ZZ4  These assemblies must comply with workmanship standards IPC-A-610 Class 2., unless otherwise specified.  [AssemblyNote]  (no BOM)

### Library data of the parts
!PCB = PCB: Manufacturer: Any; PartNumber: PMP6024; SymbolCreator: a0412235
FID1-FID4 = Fiducial: Fiducial mark.  There is nothing to buy or mount.; SymbolCreator: codlsc
Logo1 = TI_Logo: Texas Instrument Corporate Signature; SymbolCreator: codlsc
ZZ2-ZZ4 = AssemblyNote: SymbolCreator: codlsc

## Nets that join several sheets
+50V: PMP6024A_pg1 (12 pins), PMP6024A_pg2 (14 pins)
EGND: PMP6024A_pg1 (8 pins), PMP6024A_pg2 (C40.2)
ISO_15V: PMP6024A_pg1 (C16.1 Q4.2 R11.2), PMP6024A_pg2 (R52.1 R53.1)
SGND: PMP6024A_pg1 (19 pins), PMP6024A_pg2 (23 pins)

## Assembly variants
001: all parts fitted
